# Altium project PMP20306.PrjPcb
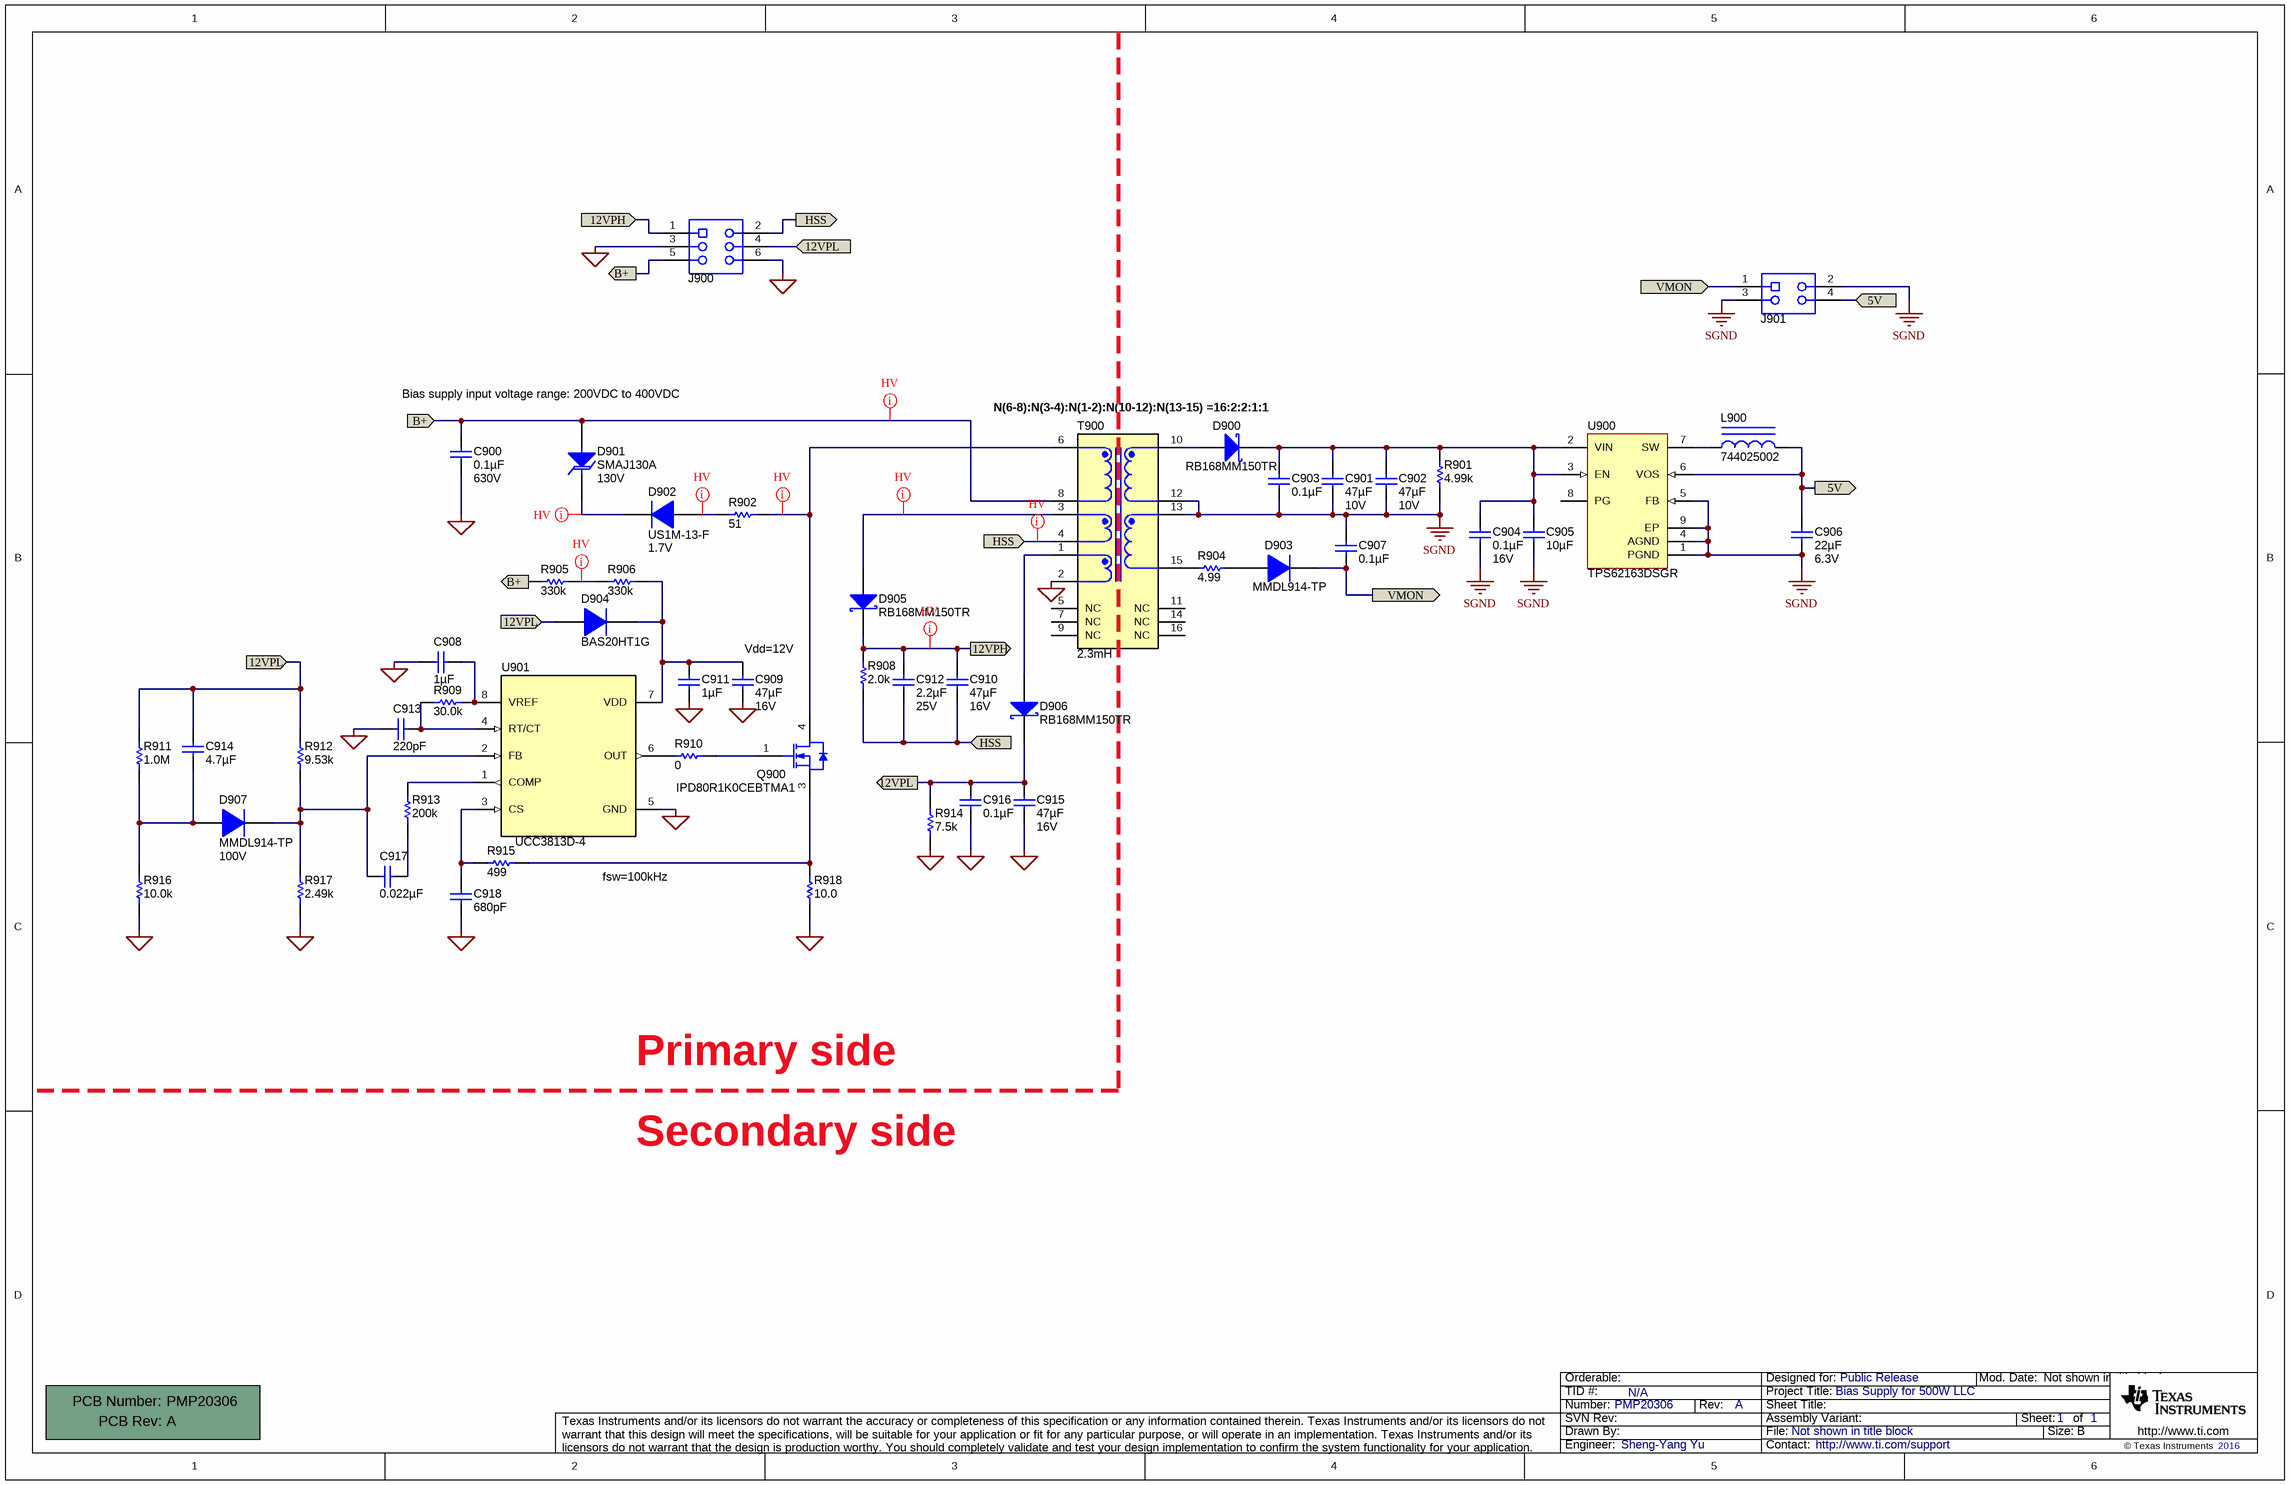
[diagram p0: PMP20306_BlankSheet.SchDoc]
TID: N/A; TechSupport: http://www.ti.com/support; SCH_Rev: A; PRJ_Title: Bias Supply for 500W LLC; PRJ_Number: PMP20306; PRJ_Engineer: Sheng-Yang Yu; PRJ_Customer: Public Release; PCB_Rev: A; PCB_Layout: Sheng-Yang Yu; CopyrightYear: 2016
1 sheet, 51 parts. Net scope: flat (ports and power ports of the same name join across sheets).
Board file: PMP20306_PCB.PcbDoc

## Sheet PMP20306_BlankSheet.SchDoc
size 431 x 279 mm; Date: Not shown in title block; ApprovedBy: Not shown in title block; CheckedBy: Not shown in title block; Author: Not shown in title block; CompanyName: Not shown in title block; Engineer: Not shown in title block; Organization: Not shown in title block; Address1: Not shown in title block; Address2: Not shown in title block; Address3: Not shown in title block; Address4: Not shown in title block; DocumentNumber: 1; Revision: Use project parameter SCH_Rev; SheetNumber: 1; SheetTotal: 1; PageSetup: Record=PageOptions¦CenterHorizontal=True¦CenterVertical=True¦PrintScale=1.00¦XCorrection=1.00¦YCorrection=1.00¦PrintKind=0¦BorderSize=5000000¦LeftOffset=0¦BottomOffset=0¦Orientation=2¦PaperLength=1000¦PaperWidth=1000¦Scale=100¦PaperSource=15¦PrintQuality=600¦MediaType=1¦DitherType=10¦PaperKind=Letter¦PrintScaleMode=1

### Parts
!PCB900  Printed Circuit Board  (value not drawn)  (mechanical)
C900  ValueDisplayed: 0.1µF  Value2: 630V  [1812]  (hidden comment: GRM43DR72J104KW01L)
C901  ValueDisplayed: 47µF  Value2: 10V  [1210_270]  (hidden comment: GRM32ER61A476KE20L)
C902  ValueDisplayed: 47µF  Value2: 10V  [1210_270]  (hidden comment: GRM32ER61A476KE20L)
C903  ValueDisplayed: 0.1µF  [0603]  (hidden comment: 06033C104JAT2A)
C904  ValueDisplayed: 0.1µF  Value2: 16V  [0402]  (hidden comment: 885012205037)
C905  ValueDisplayed: 10µF  [0805_HV]  (hidden comment: 885012207026)
C906  ValueDisplayed: 22µF  Value2: 6.3V  [0805_HV]  (hidden comment: JMK212BJ226MG-T)
C907  ValueDisplayed: 0.1µF  [0805_HV]  (hidden comment: 08055C104MAT2A)
C908  ValueDisplayed: 1µF  [1206]  (hidden comment: C1206C105K3RACTU)
C909  ValueDisplayed: 47µF  Value2: 16V  [1210_270]  (hidden comment: GRM32ER61C476KE15L)
C910  ValueDisplayed: 47µF  Value2: 16V  [1210_270]  (hidden comment: GRM32ER61C476KE15L)
C911  ValueDisplayed: 1µF  [0805_HV]  (hidden comment: CL21B105KBFNNNE)
C912  ValueDisplayed: 2.2µF  Value2: 25V  [1206]  (hidden comment: 12063D225KAT2A)
C913  ValueDisplayed: 220pF  [0603]  (hidden comment: 06031C221KAT2A)
C914  ValueDisplayed: 4.7µF  [0805_HV]  (hidden comment: 0805ZD475KAT2A)
C915  ValueDisplayed: 47µF  Value2: 16V  [1210_270]  (hidden comment: GRM32ER61C476KE15L)
C916  ValueDisplayed: 0.1µF  [0402]  (hidden comment: 885012205037)
C917  ValueDisplayed: 0.022µF  [0402]  (hidden comment: GRM155R61C223KA01D)
C918  ValueDisplayed: 680pF  [0402]  (hidden comment: GRM1555C1H681JA01D)
D900  RB168MM150TR  [SOD-123]
D901  SMAJ130A  value 130V  [SMA]
D902  US1M-13-F  value 1.7V  [SMA]
D903  MMDL914-TP  [sod-323]
D904  BAS20HT1G  [sod-323]
D905  RB168MM150TR  [SOD-123]
D906  RB168MM150TR  [SOD-123]
D907  MMDL914-TP  value 100V  [sod-323]
J900  PPPC032LJBN-RC  [Sullins_xPxC032LJBN]  (value not drawn)
J901  PPPC022LJBN-RC  [Sullins_PPPC022LJBN-RC]  (value not drawn)
L900  744025002  [WE-TPC_2828]
Q900  IPD80R1K0CEBTMA1  [DPAK]
R901  ValueDisplayed: 4.99k  [0402]  (hidden comment: CRCW04024K99FKED)
R902  ValueDisplayed: 51  [1206]  (hidden comment: CRCW120651R0JNEA)
R904  ValueDisplayed: 4.99  [0805_HV]  (hidden comment: CRCW08054R99FKEA)
R905  ValueDisplayed: 330k  [1206]  (hidden comment: CRCW1206330KJNEA)
R906  ValueDisplayed: 330k  [1206]  (hidden comment: CRCW1206330KJNEA)
R908  ValueDisplayed: 2.0k  [1206]  (hidden comment: CRCW12062K00JNEA)
R909  ValueDisplayed: 30.0k  [0603]  (hidden comment: ERJ-3EKF3002V)
R910  ValueDisplayed: 0  [0603]  (hidden comment: CRCW06030000Z0EA)
R911  ValueDisplayed: 1.0M  [0402]  (hidden comment: CRCW04021M00JNED)
R912  ValueDisplayed: 9.53k  [0402]  (hidden comment: CRCW04029K53FKED)
R913  ValueDisplayed: 200k  [0402]  (hidden comment: CRCW0402200KFKED)
R914  ValueDisplayed: 7.5k  [0402]  (hidden comment: CRCW04027K50JNED)
R915  ValueDisplayed: 499  [0402]  (hidden comment: CRCW0402499RFKED)
R916  ValueDisplayed: 10.0k  [0402]  (hidden comment: CRCW040210K0FKED)
R917  ValueDisplayed: 2.49k  [0402]  (hidden comment: CRCW04022K49FKED)
R918  ValueDisplayed: 10.0  [0603]  (hidden comment: CRCW060310R0FKEA)
T900  ValueDisplayed: 2.3mH  [Renco_RLTI-1184]  (hidden comment: RLTI-1184)
U900  TPS62163DSGR  [DSG0008A]
U901  UCC3813D-4  [D0008A_N]

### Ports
5V (in), 5V (out), 12VPH (in), 12VPH (out), 12VPL (in), 12VPL (out), B+ (in), B+ (out), HSS (in), HSS (out), VMON (in), VMON (out)

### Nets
GND_PRI: C900.2 C908.2 C909.1 C911.2 C913.1 C915.1 C916.2 C918.2 J900.3 J900.6 R914.1 R916.1 R917.1 R918.1 T900.2 U901.5(GND)
SGND: C901.1 C902.1 C903.2 C904.2 C905.2 C906.2 C907.1 J901.2 J901.3 R901.1 T900.12 T900.13 U900.1(PGND) U900.4(AGND) U900.5(FB) U900.9(EP)
5V: C906.1 J901.4 L900.2 U900.6(VOS) ; port 5V
12VPH: C910.2 C912.1 D905.1(K) J900.1 R908.2 ; port 12VPH
12VPL: C914.1 C915.2 C916.1 D904.2(A) D906.1(K) J900.4 R911.2 R912.2 R914.2 ; port 12VPL
B+: C900.1 D901.2(A) J900.5 R905.1 T900.8 ; port B+
HSS: C910.1 C912.2 J900.2 R908.1 T900.4 ; port HSS
VMON: C907.2 D903.1(K) J901.1 ; port VMON
NetC901_2: C901.2 C902.2 C903.1 C904.1 C905.1 D900.1(K) R901.2 U900.2(VIN) U900.3(EN)
NetC908_1: C908.1 R909.2 U901.8(VREF)
NetC909_2: C909.2 C911.1 D904.1(K) R906.2 U901.7(VDD)
NetC913_2: C913.2 R909.1 U901.4(RT/CT)
NetC914_2: C914.2 D907.2(A) R911.1 R916.2
NetC917_1: C917.1 R913.1
NetC917_2: C917.2 D907.1(K) R912.1 R917.2 U901.2(FB)
NetC918_1: C918.1 R915.1 U901.3(CS)
NetD900_2: D900.2(A) T900.10
NetD901_1: D901.1(K) D902.1(K)
NetD902_2: D902.2(A) R902.1
NetD903_2: D903.2(A) R904.1
NetD905_2: D905.2(A) T900.3
NetD906_2: D906.2(A) T900.1
NetL900_1: L900.1 U900.7(SW)
NetQ900_1: Q900.1(G) R910.2
NetQ900_3: Q900.3(S) R915.2 R918.2
NetQ900_4: Q900.4(D) R902.2 T900.6
NetR904_2: R904.2 T900.15
NetR905_2: R905.2 R906.1
NetR910_1: R910.1 U901.6(OUT)
NetR913_2: R913.2 U901.1(COMP)

Not connected (* = marked no-connect by the designer): T900 5(NC) 7(NC) 9(NC) 11(NC) 14(NC) 16(NC); U900 8(PG)

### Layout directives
net class HV: 12VPH, B+, HSS, NetD901_1, NetD902_2, NetD905_2, NetQ900_4, NetR905_2

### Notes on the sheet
- Bias supply input voltage range: 200VDC to 400VDC
- N(6-8):N(3-4):N(1-2):N(10-12):N(13-15) =16:2:2:1:1
- (near C909) Vdd=12V
- fsw=100kHz
- Primary side
- Secondary side

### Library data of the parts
!PCB900 = PCB: Manufacturer: Any; PartNumber: PMP20306; SymbolCreator: a0412235
C900 = GRM43DR72J104KW01L: CAP, CERM, 0.1uF, 630V, +/-10%, X7R, 1812; Manufacturer: MuRata; Polarized: N; CompType: Capacitor; U/M: EA; Cap_F: 0.0000001; Tolerance_%: 10; VDC_V: 630; TaMin_C: -55; TaMax_C: 125
C901 C902 = GRM32ER61A476KE20L: CAP, CERM, 47 µF, 10 V, +/- 10%, X5R, 1210; Manufacturer: MuRata; Polarized: N; CompType: Capacitor; Value: 47uF; U/M: EA; Cap_F: 0.000047; Tolerance_%: 10; ESR_ohm: 0.001; Value1: 0.001 ohm; TaMin_C: -55; TaMax_C: 85; Cap_Case: 1210; SizeArea_mm2: 8; SizeAreaWB_mm2: 14.7; SizeX_mm: 3.2; SizeY_mm: 2.5; SizeZ_mm: 2.7; AEC Category: Q200
C903 = 06033C104JAT2A: CAP, CERM, 0.1uF, 25V, +/-5%, X7R, 0603; Manufacturer: AVX; Polarized: N; CompType: Capacitor; U/M: EA; Cap_F: 0.0000001; Tolerance_%: 5; ESR_Ohm: 0.05; Value1: 0.05 ohm; VDC_V: 25; TaMin_C: -55; TaMax_C: 125
C904 = 885012205037: CAP, CERM, 0.1 µF, 16 V, +/- 10%, X7R, 0402; Manufacturer: Wurth Elektronik; Polarized: N; CompType: Capacitor; Value: 0.1uF; U/M: EA; Cap_F: 0.0000001; Tolerance_%: 10; Value1: Unknown; VDC_V: 16; TaMin_C: -55; TaMax_C: 125; SizeArea_mm2: 0.5; SizeAreaWB_mm2: 3; SizeX_mm: 1; SizeZ_mm: 0.6; AEC Category: Q200
C905 = 885012207026: CAP, CERM, 10 µF, 10 V, +/- 10%, X7R, 0805; Manufacturer: Wurth Elektronik; Polarized: N; CompType: Capacitor; Value: 10uF; U/M: EA; Cap_F: 0.00001; Tolerance_%: 10; Value1: Unknown; Value2: 10V; TaMin_C: -55; TaMax_C: 125; Cap_Case: 0805; SizeArea_mm2: 2.5; SizeAreaWB_mm2: 6.75; SizeX_mm: 2; SizeY_mm: 1.25; SizeZ_mm: 1.45; AEC Category: Q200
C906 = JMK212BJ226MG-T: CAP, CERM, 22 µF, 6.3 V, +/- 20%, X5R, 0805; Manufacturer: Taiyo Yuden; Polarized: N; CompType: Capacitor; Value: 22uF; U/M: EA; Cap_F: 0.000022; Tolerance_%: 20; Value1: Unknown; VDC_V: 6.3; TaMin_C: -55; TaMax_C: 85; Cap_Case: 0805; SizeArea_mm2: 2.5; SizeAreaWB_mm2: 6.75; SizeX_mm: 2; SizeY_mm: 1.25; SizeZ_mm: 1.45; AEC Category: Q200
C907 = 08055C104MAT2A: CAP, CERM, 0.1uF, 50V, +/-20%, X7R, 0805; Manufacturer: AVX; Polarized: N; CompType: Capacitor; U/M: EA; Cap_F: 0.0000001; Tolerance_%: 20; ESR_Ohm: 0.024; Value1: 0.024 ohm; VDC_V: 50; TaMin_C: -55; TaMax_C: 125; Cap_Case: 0805
C908 = C1206C105K3RACTU: CAP, CERM, 1 µF, 25 V, +/- 10%, X7R, 1206; Manufacturer: Kemet; Polarized: N; CompType: Capacitor; Value: 1uF; U/M: EA; Cap_F: 0.000001; Tolerance_%: 10; ESR_ohm: 0.011; Value1: 0.011 ohm; VDC_V: 25; Value2: 25V; IRMS_A: 3.55; TaMin_C: -55; TaMax_C: 125; SizeArea_mm2: 5.12; SizeAreaWB_mm2: 10.92; SizeX_mm: 3.2; SizeY_mm: 1.6; SizeZ_mm: 1.35; AEC Category: Q200
C909 C910 C915 = GRM32ER61C476KE15L: CAP, CERM, 47 µF, 16 V, +/- 10%, X5R, 1210; Manufacturer: MuRata; Polarized: N; CompType: Capacitor; Value: 47uF; U/M: EA; Cap_F: 0.000047; Tolerance_%: 10; Value1: Unknown; VDC_V: 16; TaMin_C: -55; TaMax_C: 85; Cap_Case: 1210; SizeArea_mm2: 8; SizeAreaWB_mm2: 14.7; SizeX_mm: 3.2; SizeY_mm: 2.5; SizeZ_mm: 2.7; AEC Category: Q200
C911 = CL21B105KBFNNNE: CAP, CERM, 1 µF, 50 V, +/- 10%, X7R, 0805; Manufacturer: Samsung Electro-Mechanics; Polarized: N; CompType: Capacitor; Value: 1uF; U/M: EA; Cap_F: 0.000001; Tolerance_%: 10; Value1: Unknown; VDC_V: 50; Value2: 50V; TaMin_C: -55; TaMax_C: 125; Cap_Case: 0805; AEC Category: Q200
C912 = 12063D225KAT2A: CAP, CERM, 2.2 µF, 25 V, +/- 10%, X5R, 1206; Manufacturer: AVX; Polarized: N; CompType: Capacitor; Value: 2.2uF; U/M: EA; Cap_F: 0.0000022; Tolerance_%: 10; ESR_ohm: 0.016; Value1: 0.016 ohm; VDC_V: 25; TaMin_C: -55; TaMax_C: 85; AEC Category: Q200
C913 = 06031C221KAT2A: CAP, CERM, 220pF, 100V, +/-10%, X7R, 0603; Manufacturer: AVX; Polarized: N; CompType: Capacitor; U/M: EA; Cap_F: 0.00000000022; Tolerance_%: 10; ESR_Ohm: 0.579; Value1: 0.579 ohm; VDC_V: 100; TaMin_C: -55; TaMax_C: 125
C914 = 0805ZD475KAT2A: CAP, CERM, 4.7uF, 10V, +/-10%, X5R, 0805; Manufacturer: AVX; Polarized: N; CompType: Capacitor; U/M: EA; Cap_F: 0.0000047; Tolerance_%: 10; ESR_Ohm: 0.007; Value1: 0.007 ohm; TaMin_C: -55; TaMax_C: 85; Cap_Case: 0805
C916 = 885012205037: CAP, CERM, 0.1 µF, 16 V, +/- 10%, X7R, 0402; Manufacturer: Wurth Elektronik; Polarized: N; CompType: Capacitor; Value: 0.1uF; U/M: EA; Cap_F: 0.0000001; Tolerance_%: 10; Value1: Unknown; VDC_V: 16; Value2: 16V; TaMin_C: -55; TaMax_C: 125; SizeArea_mm2: 0.5; SizeAreaWB_mm2: 3; SizeX_mm: 1; SizeZ_mm: 0.6; AEC Category: Q200
C917 = GRM155R61C223KA01D: CAP, CERM, 0.022 µF, 16 V, +/- 10%, X5R, 0402; Manufacturer: MuRata; Polarized: N; CompType: Capacitor; Value: 0.022uF; U/M: EA; Cap_F: 0.000000022; Tolerance_%: 10; Value1: Unknown; VDC_V: 16; Value2: 16V; TaMin_C: -55; TaMax_C: 85; SizeArea_mm2: 0.5; SizeAreaWB_mm2: 3; SizeX_mm: 1; SizeZ_mm: 0.6; AEC Category: Q200
C918 = GRM1555C1H681JA01D: CAP, CERM, 680 pF, 50 V, +/- 5%, C0G/NP0, 0402; Manufacturer: MuRata; Polarized: N; CompType: Capacitor; Value: 680pF; U/M: EA; Cap_F: 0.00000000068; Tolerance_%: 5; Value1: Unknown; VDC_V: 50; Value2: 50V; TaMin_C: -55; TaMax_C: 125; SizeArea_mm2: 0.5; SizeAreaWB_mm2: 3; SizeX_mm: 1; SizeZ_mm: 0.6; AEC Category: Q200
D900 D905 D906 = RB160M-60TR: DIODE SCHOTTKY 150V 1A PMDU; Manufacturer: Rohm; U/M: EA; Vf_V: 0.55; Value: 60V; Value2: 0.55V; Io_A: 1; Vr_V: 60; TJmax_C: 150; SizeAreaWB_mm2: 13.095; SizeArea_mm2: 6.545; SizeX_mm: 3.85; SizeY_mm: 1.7; SizeZ_mm: 1.35; AEC Category: Q101
D901 = SMAJ120A: DIODE TVS 130V 400W UNI 5% SMD; Manufacturer: Littelfuse; U/M: EA; Power_W: 400; Vr_V: 130; RJA_CperW: 120
D902 = US1M-13-F: Diode, Ultrafast, 1000V, 1A, SMA; Manufacturer: Diodes Inc.; U/M: EA; Vf_V: 1.7; Io_A: 1; Vr_V: 1000; TJmax_C: 150; RJC_CperW: 30
D903 = MMDL914-TP: Diode, Switching, 100 V, 0.2 A, SOD-323; Manufacturer: Micro Commercial Components; U/M: EA; Vf_V: 1; Value: 100V; Value1: 0.2A; Value2: 1V; Io_A: 0.2; Vr_V: 100; TJmax_C: 150; AEC Category: Q101
D904 = BAS316,115: DIODE SWITCH 200V 200MA SOD323; U/M: EA; Vf_V: 1.4; Value1: 0.25A; Vr_V: 100; Value2: 100V; TJmax_C: 150; Type: Ultrafast
D907 = MMDL914-TP: Diode, Switching, 100V, 0.2A, SOD-323; Manufacturer: Micro Commercial Components; U/M: EA; Vf_V: 1; Value2: 1V; Io_A: 0.2; Vr_V: 100; TJmax_C: 150; RJC_CperW: 635
J900 = PPPC032LJBN-RC: Receptacle, 2.54mm, 3x2, Gold, R/A, TH; Manufacturer: Sullins Connector Solutions; SymbolCreator: Altium; U/M: EA
J901 = PPPC022LJBN-RC: CONN FEMALE 4POS DL .1" R/A GOLD; Manufacturer: Sullins Connector Solutions; SymbolCreator: a0411947; CompType: Receptacle; U/M: EA
L900 = 744025002: Inductor, Shielded Drum Core, Ferrite, 2.2 µH, 1.8 A, 0.057 ohm, SMD; Manufacturer: Wurth Elektronik eiSos; Value: 2.2uH; Ind_H: 2.2E-6; ValueDisplayed: 2.2µH; Imax_A: 1.8; Irms: 1.8A @ 40C rise; Isat: 2.4A @ 35% inductance drop; DCR_ohm: 0.057; Value2: 1.8A
Q900 = IPD80R1K0CEBTMA1: MOSFET, N-CH, 800 V, 5.7 A, DPAK; Manufacturer: Infineon Technologies; Alternate Manufacturer: None; U/M: EA; ChType: N; Value: 800V; VdsMax_V: 800; Value1: ? ohm; Value2: 31 nC; QgTyp_nC: 31; Vgs_V: 20; IdsMax_A: 5.7; SizeAreaWB_mm2: 101.7114; SizeArea_mm2: 64.8114; SizeX_mm: 9.91; SizeY_mm: 6.54; SizeZ_mm: 2.29; AEC Category: Q101
R901 = CRCW04024K99FKED: RES, 4.99 k, 1%, 0.063 W, 0402; Manufacturer: Vishay-Dale; CompType: Resistor; Value: 4.99k; Res_ohm: 4990; Value_Code: 4k99; Tolerance_%: 1; Power_W: 0.063; Value2: 0.063W; VDC_V: 50; TempCo: 100 ppm/C; EIA_Code: E96; U/M: EA; AEC Category: Q200
R902 = CRCW120651R0JNEA: RES, 51, 5%, 0.25 W, 1206; Manufacturer: Vishay-Dale; CompType: Resistor; Value: 51; Value_Code: 51R0; Tolerance_%: 5; Power_W: 0.25; Value2: 0.25W; VDC_V: 200; TempCo: 200 ppm/C; EIA_Code: E24; U/M: EA; AEC Category: Q200
R904 = CRCW08054R99FKEA: RES, 4.99, 1%, 0.125 W, 0805; Manufacturer: Vishay-Dale; CompType: Resistor; Value: 4.99; Value_Code: 4R99; Tolerance_%: 1; Power_W: 0.125; Value2: 0.125W; VDC_V: 150; TempCo: 100 ppm/C; EIA_Code: E96; U/M: EA
R905 R906 = CRCW1206330KJNEA: RES, 330 k, 5%, 0.25 W, 1206; Manufacturer: Vishay-Dale; CompType: Resistor; Value: 330k; Res_ohm: 330000; Tolerance_%: 5; Power_W: 0.25; Value2: 0.25W; VDC_V: 200; TempCo: 200 ppm/C; EIA_Code: E24; U/M: EA; AEC Category: Q200
R908 = CRCW12062K00JNEA: RES, 2.0 k, 5%, 0.25 W, 1206; Manufacturer: Vishay-Dale; CompType: Resistor; Value: 2.0k; Res_ohm: 2000; Value_Code: 2k00; Tolerance_%: 5; Power_W: 0.25; Value2: 0.25W; VDC_V: 200; TempCo: 200 ppm/C; EIA_Code: E24; U/M: EA; AEC Category: Q200
R909 = ERJ-3EKF3002V: RES, 30.0 k, 1%, 0.1 W, AEC-Q200 Grade 0, 0603; Manufacturer: Panasonic; CompType: Resistor; Value: 30.0k; Res_ohm: 30000; Value_Code: 30k0; Tolerance_%: 1; Power_W: 0.1; Value2: 0.1W; VDC_V: 75; TempCo: 100 ppm/C; U/M: EA; AEC Category: Q200; AEC Qualified: Y; AEC Grade: 0
R910 = CRCW06030000Z0EA: RES, 0, 5%, 0.1 W, 0603; Manufacturer: Vishay-Dale; CompType: Resistor; Value: 0; Value_Code: 0000; Tolerance_%: 5; Power_W: 0.1; Value2: 0.1W; VDC_V: 75; TempCo: 200 ppm/C; EIA_Code: E24; U/M: EA; AEC Category: Q200
R911 = CRCW04021M00JNED: RES, 1.0 M, 5%, 0.063 W, 0402; Manufacturer: Vishay-Dale; CompType: Resistor; Value: 1.0Meg; Res_ohm: 1000000; Value_Code: 1M00; Tolerance_%: 5; Power_W: 0.063; Value2: 0.063W; VDC_V: 50; TempCo: 200 ppm/C; EIA_Code: E24; U/M: EA; AEC Category: Q200
R912 = CRCW04029K53FKED: RES, 9.53 k, 1%, 0.063 W, 0402; Manufacturer: Vishay-Dale; CompType: Resistor; Value: 9.53k; Res_ohm: 9530; Value_Code: 9k53; Tolerance_%: 1; Power_W: 0.063; Value2: 0.063W; VDC_V: 50; TempCo: 100 ppm/C; EIA_Code: E96; U/M: EA; AEC Category: Q200
R913 = CRCW0402200KFKED: RES, 200 k, 1%, 0.063 W, 0402; Manufacturer: Vishay-Dale; CompType: Resistor; Value: 200k; Res_ohm: 200000; Tolerance_%: 1; Power_W: 0.063; Value2: 0.063W; VDC_V: 50; TempCo: 100 ppm/C; EIA_Code: E96; U/M: EA; AEC Category: Q200
R914 = CRCW04027K50JNED: RES, 7.5 k, 5%, 0.063 W, 0402; Manufacturer: Vishay-Dale; CompType: Resistor; Value: 7.5k; Res_ohm: 7500; Value_Code: 7k50; Tolerance_%: 5; Power_W: 0.063; Value2: 0.063W; VDC_V: 50; TempCo: 200 ppm/C; EIA_Code: E24; U/M: EA; AEC Category: Q200
R915 = CRCW0402499RFKED: RES, 499, 1%, 0.063 W, 0402; Manufacturer: Vishay-Dale; CompType: Resistor; Value: 499; Value_Code: 499R; Tolerance_%: 1; Power_W: 0.063; Value2: 0.063W; VDC_V: 50; TempCo: 100 ppm/C; EIA_Code: E96; U/M: EA; AEC Category: Q200
R916 = CRCW040210K0FKED: RES, 10.0 k, 1%, 0.063 W, 0402; Manufacturer: Vishay-Dale; CompType: Resistor; Value: 10.0k; Res_ohm: 10000; Value_Code: 10k0; Tolerance_%: 1; Power_W: 0.063; Value2: 0.063W; VDC_V: 50; TempCo: 100 ppm/C; EIA_Code: E96; U/M: EA; AEC Category: Q200
R917 = CRCW04022K49FKED: RES, 2.49 k, 1%, 0.063 W, 0402; Manufacturer: Vishay-Dale; CompType: Resistor; Value: 2.49k; Res_ohm: 2490; Value_Code: 2k49; Tolerance_%: 1; Power_W: 0.063; Value2: 0.063W; VDC_V: 50; TempCo: 100 ppm/C; EIA_Code: E96; U/M: EA; AEC Category: Q200
R918 = CRCW060310R0FKEA: RES, 10.0, 1%, 0.1 W, 0603; Manufacturer: Vishay-Dale; CompType: Resistor; Value: 10.0; Res_ohm: 10; Value_Code: 10R0; Tolerance_%: 1; Power_W: 0.1; Value2: 0.1W; VDC_V: 75; TempCo: 100 ppm/C; EIA_Code: E96; U/M: EA; AEC Category: Q200
T900 = RLTI-1184: Transformer, 2300 uH, SMT; Manufacturer: Renco Electronics; SymbolCreator: Altium; Value: 2.3mH; Lp: 2300; DCR_ohm: 2.15; Rs1: 0.06; SizeAreaWB_mm2: 342.039456; SizeArea_mm2: 271.999456; SizeX_mm: 17.272; SizeY_mm: 15.748; SizeZ_mm: 13.208
U900 = TPS62163DSGR: Buck Step Down Regulator with 3 to 17 V Input and 5 V Output, -40 to 85 degC, 8-Pin WSON (DSG), Green (RoHS & no Sb/Br); Manufacturer: Texas Instruments; Alternate Manufacturer: None; Alternate PartNumber: Equivalent; Duty Cycle(Max)(%): 100; Iout(Max)(A): 1; Iq(Typ)(mA): 0.017; Preset Vout(V): 5; Rating: Catalog; SubFamily: Step-Down Regulator; Switch Current Limit(Typ)(A): 1.8; Synchronous Rectification: TRUE; Vin(Max)(V): 17; Vin(Min)(V): 3
U901 = UCC28C42DR: IC REG CTRLR PWM CM 8SOIC; Manufacturer: Texas Instruments; SymbolCreator: a0411947; U/M: EA

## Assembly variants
001: not fitted FID1 FID2 FID3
